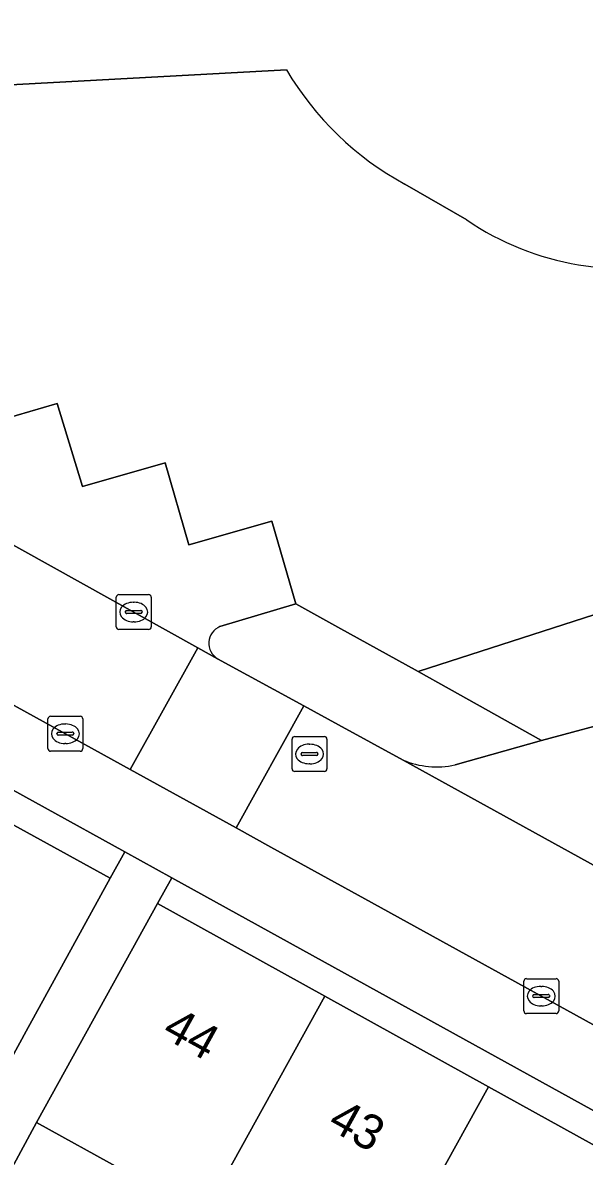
# Model space of a CAD drawing. Extents: x 158352 to 159489, y 383828 to 384603.
# Drawn here: x 158928.82 to 158944.92, y 384098.81 to 384131.29 of the extents above; entities that cross this region are included whole.
import ezdxf

# ---------------------------------------------------------------- set-up
doc = ezdxf.new("R2010")
doc.units = 0
for name, color, linetype in [('IMGEO_Erf', 7, 'Continuous'), ('IMGEO_Groenvoorziening', 7, 'Continuous'), ('IMGEO_Kolk', 7, 'Continuous'), ('IMGEO_Pand', 7, 'Continuous'), ('IMGEO_Pand_nummerreeks', 7, 'Continuous'), ('IMGEO_Parkeervlak_open', 7, 'Continuous'), ('IMGEO_Rijbaan_lokaal_open', 7, 'Continuous'), ('IMGEO_Rioolput', 7, 'Continuous'), ('IMGEO_Voetpad_gesloten', 7, 'Continuous'), ('IMGEO_Voetpad_halfverhard', 7, 'Continuous'), ('IMGEO_Voetpad_open', 7, 'Continuous')]:
    doc.layers.add(name, color=color, linetype=linetype)

msp = doc.modelspace()

# ---------------------------------------------------------------- linework, layer by layer
at = {"layer": 'IMGEO_Erf'}
for points in [[(158927.171, 384110.055), (158926.75, 384109.287), (158931.33, 384106.772), (158931.748, 384107.529)], [(158933.094, 384106.786), (158932.685, 384106.046), (158937.479, 384103.394), (158942.168, 384100.8), (158946.855, 384098.207), (158951.544, 384095.613), (158956.233, 384093.019), (158960.921, 384090.426), (158965.609, 384087.832), (158970.298, 384085.238), (158975.09, 384082.587), (158975.522, 384083.371)]]:
    msp.add_lwpolyline(points, close=True, dxfattribs=at)
msp.add_lwpolyline([(158931.669, 384098.419), (158929.216, 384099.776), (158921.794, 384086.055)], dxfattribs=at)
at = {"layer": 'IMGEO_Groenvoorziening'}
for points in [[(158936.38, 384129.934), (158915.645, 384128.805), (158915.761, 384126.104), (158918.255, 384124.726), (158920.621, 384125.421), (158921.351, 384123.058), (158923.66, 384123.737), (158924.388, 384121.359), (158926.764, 384122.024), (158927.453, 384119.69), (158929.807, 384120.373), (158930.531, 384118.002), (158932.905, 384118.676), (158933.583, 384116.324), (158935.963, 384117.003), (158936.647, 384114.639), (158937.851, 384113.971), (158940.156, 384112.693), (158946.102, 384114.62), (158950.901, 384123.26)], [(158941.546, 384125.635), (158939.772, 384126.662)]]:
    msp.add_lwpolyline(points, dxfattribs=at)
for centre, radius, start, end in [((158944.05, 384134.491), 8.922, 210.7162, 241.347), ((158946.139, 384132.445), 8.214, 236.0015, 284.5409)]:
    msp.add_arc(centre, radius, start, end, dxfattribs=at)
at = {"layer": 'IMGEO_Kolk'}
for p, q in [((158931.579, 384114.9), (158932.431, 384114.9)), ((158931.504, 384113.974), (158931.504, 384114.826)), ((158931.992, 384114.68), (158932.017, 384114.68)), ((158932.505, 384114.826), (158932.505, 384113.974)), ((158931.763, 384114.394), (158931.763, 384114.406)), ((158932.201, 384114.357), (158931.803, 384114.357)), ((158931.806, 384114.443), (158932.204, 384114.443)), ((158932.247, 384114.406), (158932.247, 384114.394)), ((158932.015, 384114.12), (158931.99, 384114.12)), ((158932.431, 384113.9), (158931.579, 384113.9)), ((158929.544, 384110.487), (158929.544, 384111.339)), ((158929.619, 384111.413), (158930.471, 384111.413)), ((158930.545, 384111.339), (158930.545, 384110.487)), ((158930.032, 384111.193), (158930.057, 384111.193)), ((158929.803, 384110.907), (158929.803, 384110.919)), ((158930.241, 384110.87), (158929.843, 384110.87)), ((158929.846, 384110.956), (158930.244, 384110.956)), ((158930.287, 384110.919), (158930.287, 384110.907)), ((158930.471, 384110.413), (158929.619, 384110.413)), ((158930.055, 384110.633), (158930.03, 384110.633)), ((158943.257, 384103.896), (158944.109, 384103.896)), ((158943.182, 384102.97), (158943.182, 384103.822)), ((158943.67, 384103.676), (158943.695, 384103.676)), ((158944.183, 384103.822), (158944.183, 384102.97)), ((158943.441, 384103.39), (158943.441, 384103.402)), ((158943.879, 384103.353), (158943.481, 384103.353)), ((158943.484, 384103.439), (158943.882, 384103.439)), ((158943.925, 384103.402), (158943.925, 384103.39)), ((158944.109, 384102.896), (158943.257, 384102.896)), ((158943.693, 384103.116), (158943.668, 384103.116))]:
    msp.add_line(p, q, dxfattribs=at)
for points in [[(158931.579, 384114.9), (158932.431, 384114.9)], [(158931.504, 384113.974), (158931.504, 384114.826)], [(158932.505, 384114.826), (158932.505, 384113.974)], [(158932.431, 384113.9), (158931.579, 384113.9)], [(158929.544, 384110.487), (158929.544, 384111.339)], [(158929.619, 384111.413), (158930.471, 384111.413)], [(158930.545, 384111.339), (158930.545, 384110.487)], [(158930.471, 384110.413), (158929.619, 384110.413)], [(158943.257, 384103.896), (158944.109, 384103.896)], [(158943.182, 384102.97), (158943.182, 384103.822)], [(158944.183, 384103.822), (158944.183, 384102.97)], [(158944.109, 384102.896), (158943.257, 384102.896)]]:
    msp.add_lwpolyline(points, dxfattribs=at)
for centre, radius, start, end in [((158931.581, 384114.824), 0.0765, 91.552, 178.448), ((158931.581, 384114.824), 0.0765, 91.552, 178.448), ((158932.429, 384114.824), 0.0765, 1.552, 88.448), ((158932.429, 384114.824), 0.0765, 1.552, 88.448), ((158931.803, 384114.403), 0.0403, 85.8775, 175.7526), ((158931.8, 384114.393), 0.0366, 178.938, 274.7102), ((158932.204, 384114.4), 0.043, 264.8664, 352.4533), ((158932.208, 384114.405), 0.0386, 1.7309, 96.639), ((158931.581, 384113.976), 0.0765, 181.552, 268.448), ((158931.581, 384113.976), 0.0765, 181.552, 268.448), ((158932.429, 384113.976), 0.0765, 271.552, 358.448), ((158932.429, 384113.976), 0.0765, 271.552, 358.448), ((158929.621, 384111.337), 0.0765, 91.552, 178.448), ((158929.621, 384111.337), 0.0765, 91.552, 178.448), ((158930.469, 384111.337), 0.0765, 1.552, 88.448), ((158930.469, 384111.337), 0.0765, 1.552, 88.448), ((158929.843, 384110.916), 0.0403, 85.8775, 175.7526), ((158929.84, 384110.906), 0.0366, 178.938, 274.7102), ((158930.244, 384110.913), 0.043, 264.8664, 352.4533), ((158930.248, 384110.918), 0.0386, 1.7309, 96.639), ((158929.621, 384110.489), 0.0765, 181.552, 268.448), ((158929.621, 384110.489), 0.0765, 181.552, 268.448), ((158930.469, 384110.489), 0.0765, 271.552, 358.448), ((158930.469, 384110.489), 0.0765, 271.552, 358.448), ((158943.259, 384103.82), 0.0765, 91.552, 178.448), ((158943.259, 384103.82), 0.0765, 91.552, 178.448), ((158944.107, 384103.82), 0.0765, 1.552, 88.448), ((158944.107, 384103.82), 0.0765, 1.552, 88.448), ((158943.481, 384103.399), 0.0403, 85.8775, 175.7526), ((158943.478, 384103.389), 0.0366, 178.938, 274.7102), ((158943.882, 384103.396), 0.043, 264.8664, 352.4533), ((158943.886, 384103.401), 0.0386, 1.7309, 96.639), ((158943.259, 384102.972), 0.0765, 181.552, 268.448), ((158943.259, 384102.972), 0.0765, 181.552, 268.448), ((158944.107, 384102.972), 0.0765, 271.552, 358.448), ((158944.107, 384102.972), 0.0765, 271.552, 358.448)]:
    msp.add_arc(centre, radius, start, end, dxfattribs=at)
for centre, major_axis, ratio, start_param, end_param in [((158931.991, 384114.4), (-0.387, 0.002), 0.722429, 4.712389, 7.853982), ((158932.016, 384114.4), (-0.39, 0.002), 0.717154, 1.570796, 4.712389), ((158930.031, 384110.913), (-0.387, 0.002), 0.722429, 4.712389, 7.853982), ((158930.056, 384110.913), (-0.39, 0.002), 0.717154, 1.570796, 4.712389), ((158943.669, 384103.396), (-0.387, 0.002), 0.722429, 4.712389, 7.853982), ((158943.694, 384103.396), (-0.39, 0.002), 0.717154, 1.570796, 4.712389)]:
    msp.add_ellipse(centre, major_axis=major_axis, ratio=ratio, start_param=start_param, end_param=end_param, dxfattribs=at)
at = {"layer": 'IMGEO_Pand'}
for points in [[(158921.032, 384099.437), (158923.499, 384098.095), (158925.461, 384101.702), (158927.837, 384100.41), (158928.924, 384102.39), (158931.33, 384106.772), (158926.75, 384109.287), (158927.171, 384110.055), (158926.933, 384110.185), (158921.119, 384099.596)], [(158937.479, 384103.394), (158932.685, 384106.046), (158930.265, 384101.672), (158929.216, 384099.776), (158931.669, 384098.419), (158929.589, 384094.659), (158931.93, 384093.364), (158932.034, 384093.551)], [(158938.691, 384094.516), (158938.817, 384094.745), (158942.168, 384100.8), (158937.479, 384103.394), (158932.034, 384093.551), (158931.93, 384093.364), (158934.541, 384091.919), (158936.613, 384095.666)], [(158938.691, 384094.516), (158940.951, 384093.266), (158938.852, 384089.471), (158941.279, 384088.128), (158941.432, 384088.404), (158946.855, 384098.207), (158942.168, 384100.8), (158938.817, 384094.745)]]:
    msp.add_lwpolyline(points, close=True, dxfattribs=at)
at = {"layer": 'IMGEO_Parkeervlak_open'}
for points in [[(158934.475, 384113.984), (158936.647, 384114.639), (158935.963, 384117.003), (158933.583, 384116.324), (158932.905, 384118.676), (158930.531, 384118.002), (158929.807, 384120.373), (158927.453, 384119.69), (158926.764, 384122.024), (158924.388, 384121.359), (158923.66, 384123.737), (158921.351, 384123.058), (158920.621, 384125.421), (158918.255, 384124.726), (158915.722, 384123.984)], [(158914.578, 384124.093), (158933.844, 384113.376), (158934.408, 384113.062)], [(158955.306, 384106.336), (158952.942, 384105.627), (158952.235, 384108.002), (158949.857, 384107.343), (158949.177, 384109.71), (158946.8, 384109.035), (158946.105, 384111.373), (158943.691, 384110.724), (158941.211, 384110.023)], [(158939.722, 384110.159), (158962.964, 384097.342)]]:
    msp.add_lwpolyline(points, dxfattribs=at)
for centre, radius, start, end in [((158934.671, 384113.506), 0.516, 112.3001, 239.3874), ((158940.681, 384112.443), 2.478, 247.2196, 282.3429)]:
    msp.add_arc(centre, radius, start, end, dxfattribs=at)
at = {"layer": 'IMGEO_Rijbaan_lokaal_open'}
msp.add_lwpolyline([(158906.767, 384123.744), (158931.899, 384109.893), (158933.844, 384113.376), (158914.578, 384124.093), (158911.925, 384125.545)], dxfattribs=at)
for points in [[(158934.943, 384108.215), (158936.878, 384111.713), (158934.408, 384113.062), (158933.844, 384113.376), (158931.899, 384109.893)], [(158962.964, 384097.342), (158939.722, 384110.159), (158937.868, 384111.172), (158936.878, 384111.713), (158934.943, 384108.215), (158935.936, 384107.668), (158938.625, 384106.185), (158984.088, 384081.129), (158986.007, 384084.613), (158984.881, 384085.238), (158964.795, 384096.313)]]:
    msp.add_lwpolyline(points, close=True, dxfattribs=at)
at = {"layer": 'IMGEO_Rioolput'}
for p, q in [((158936.541, 384109.907), (158936.541, 384110.759)), ((158936.616, 384110.833), (158937.468, 384110.833)), ((158937.542, 384110.759), (158937.542, 384109.907)), ((158936.8, 384110.327), (158936.8, 384110.339)), ((158936.843, 384110.376), (158937.241, 384110.376)), ((158937.029, 384110.613), (158937.054, 384110.613)), ((158937.284, 384110.339), (158937.284, 384110.327)), ((158937.238, 384110.29), (158936.84, 384110.29)), ((158937.052, 384110.053), (158937.027, 384110.053)), ((158937.468, 384109.833), (158936.616, 384109.833))]:
    msp.add_line(p, q, dxfattribs=at)
for points in [[(158936.541, 384109.907), (158936.541, 384110.759)], [(158936.616, 384110.833), (158937.468, 384110.833)], [(158937.542, 384110.759), (158937.542, 384109.907)], [(158937.468, 384109.833), (158936.616, 384109.833)]]:
    msp.add_lwpolyline(points, dxfattribs=at)
for centre, radius, start, end in [((158936.618, 384110.757), 0.0765, 91.552, 178.448), ((158936.618, 384110.757), 0.0765, 91.552, 178.448), ((158937.466, 384110.757), 0.0765, 1.552, 88.448), ((158937.466, 384110.757), 0.0765, 1.552, 88.448), ((158936.84, 384110.336), 0.0403, 85.8775, 175.7526), ((158937.245, 384110.338), 0.0386, 1.7309, 96.639), ((158936.837, 384110.326), 0.0366, 178.938, 274.7102), ((158937.241, 384110.333), 0.043, 264.8664, 352.4533), ((158936.618, 384109.909), 0.0765, 181.552, 268.448), ((158936.618, 384109.909), 0.0765, 181.552, 268.448), ((158937.466, 384109.909), 0.0765, 271.552, 358.448), ((158937.466, 384109.909), 0.0765, 271.552, 358.448)]:
    msp.add_arc(centre, radius, start, end, dxfattribs=at)
for centre, major_axis, ratio, start_param, end_param in [((158937.028, 384110.333), (-0.387, 0.002), 0.722429, 4.712389, 7.853982), ((158937.053, 384110.333), (-0.39, 0.002), 0.717154, 1.570796, 4.712389)]:
    msp.add_ellipse(centre, major_axis=major_axis, ratio=ratio, start_param=start_param, end_param=end_param, dxfattribs=at)
at = {"layer": 'IMGEO_Voetpad_gesloten'}
msp.add_lwpolyline([(158950.901, 384123.26), (158946.102, 384114.62), (158940.156, 384112.693), (158941.041, 384112.203), (158943.691, 384110.724), (158946.105, 384111.373), (158949.814, 384112.922), (158952.93, 384118.493), (158955.021, 384122.136), (158969.705, 384149.635)], dxfattribs=at)
at = {"layer": 'IMGEO_Voetpad_halfverhard'}
for points in [[(158935.845, 384132.635), (158925.46, 384132.091), (158915.543, 384131.49), (158915.637, 384129.002), (158915.645, 384128.805), (158936.38, 384129.934)], [(158939.772, 384126.662), (158941.546, 384125.635)]]:
    msp.add_lwpolyline(points, dxfattribs=at)
for centre, radius, start, end in [((158944.05, 384134.491), 8.922, 210.7162, 241.347), ((158946.139, 384132.445), 8.214, 236.0015, 284.5409)]:
    msp.add_arc(centre, radius, start, end, dxfattribs=at)
at = {"layer": 'IMGEO_Voetpad_open'}
for points in [[(158898.923, 384125.588), (158908.084, 384120.639), (158912.836, 384118.03), (158913.048, 384117.914), (158912.88, 384117.607), (158917.382, 384115.135), (158922.006, 384112.596), (158922.13, 384112.822), (158922.219, 384112.773), (158926.933, 384110.185), (158927.171, 384110.055), (158931.748, 384107.529), (158933.094, 384106.786), (158975.522, 384083.371)], [(159000, 384072.359), (158986.803, 384079.633), (158984.088, 384081.129), (158938.625, 384106.185), (158935.936, 384107.668), (158934.943, 384108.215), (158931.899, 384109.893), (158906.767, 384123.744)], [(158941.211, 384110.023), (158943.691, 384110.724), (158941.041, 384112.203), (158940.156, 384112.693), (158937.851, 384113.971), (158936.647, 384114.639), (158934.475, 384113.984)], [(158934.408, 384113.062), (158936.878, 384111.713), (158937.868, 384111.172), (158939.722, 384110.159)], [(158921.794, 384086.055), (158929.216, 384099.776), (158930.265, 384101.672), (158932.685, 384106.046), (158933.094, 384106.786), (158931.748, 384107.529), (158931.33, 384106.772), (158928.924, 384102.39), (158927.837, 384100.41), (158920.462, 384086.776)]]:
    msp.add_lwpolyline(points, dxfattribs=at)
for centre, radius, start, end in [((158934.671, 384113.506), 0.516, 112.3001, 239.3874), ((158940.681, 384112.443), 2.478, 247.2196, 282.3429)]:
    msp.add_arc(centre, radius, start, end, dxfattribs=at)

# ---------------------------------------------------------------- texts
at = {"layer": 'IMGEO_Pand_nummerreeks'}
for s, rotation, p in [('44', 331.0399, (158932.771, 384102.249)), ('43', 331.0491, (158937.519, 384099.622))]:
    msp.add_text(s, height=1, rotation=rotation, dxfattribs=at).set_placement(p)

doc.saveas('drawing.dxf')
